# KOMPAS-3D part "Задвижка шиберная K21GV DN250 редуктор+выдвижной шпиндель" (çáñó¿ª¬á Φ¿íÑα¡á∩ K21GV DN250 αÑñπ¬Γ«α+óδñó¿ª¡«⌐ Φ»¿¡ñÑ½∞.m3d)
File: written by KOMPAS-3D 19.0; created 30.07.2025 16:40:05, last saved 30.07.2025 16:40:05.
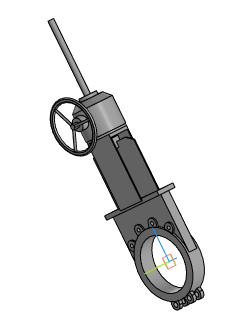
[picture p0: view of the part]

Document properties: Полное имя файла: Задвижка шиберная K21GV DN250 редуктор+выдвижной шпиндель.a3d

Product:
- Part/product: Задвижка шиберная K21GV DN250 редуктор+выдвижной шпиндель
    Масса: 84.7102

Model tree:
1. Операция без истории:1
